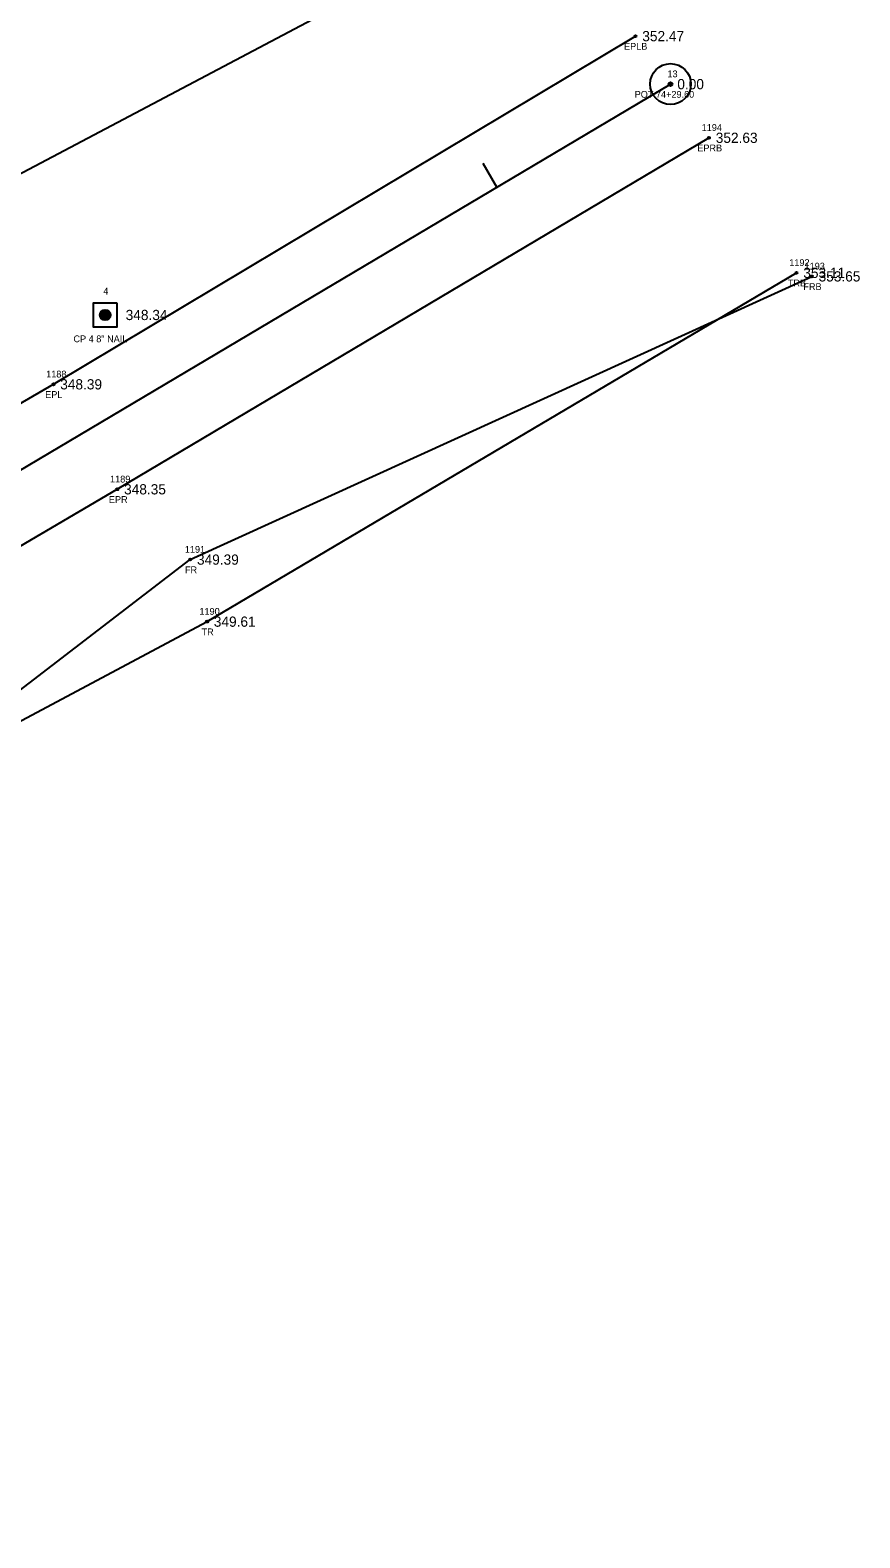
# Model space of a CAD drawing. Extents: x 2231119 to 2232595, y 1035731 to 1037094.
# Drawn here: x 2232187.1 to 2232308.8, y 1036650 to 1036871.1 of the extents above; entities that cross this region are included whole.
import ezdxf

# ---------------------------------------------------------------- set-up
doc = ezdxf.new("R2010")
doc.units = 0
for name, color, linetype in [('RD_EX_Fence_Other', 7, 'Continuous'), ('RD_EX_Fence_Other_txCode', 7, 'Continuous'), ('RD_EX_Road', 7, 'Continuous'), ('RD_EX_Road_txCode', 7, 'Continuous'), ('RD_EX_TX_Fence_Other_ELEV', 7, 'Continuous'), ('RD_EX_TX_Road_ELEV', 7, 'Continuous'), ('RD_EX_TX_VEG_ELEV', 7, 'Continuous'), ('RD_EX_VEG', 7, 'Continuous'), ('RD_EX_VEG_txCode', 7, 'Continuous'), ('RD_HC_Cl', 7, 'Continuous'), ('RD_HC_Data', 7, 'Continuous'), ('RD_HC_Data_Tic', 7, 'Continuous'), ('RD_HC_Survey', 7, 'Continuous'), ('RD_HC_Survey_ELEV', 7, 'Continuous'), ('RD_HC_Survey_txCode', 7, 'Continuous'), ('RD_HC_txCode', 7, 'Continuous'), ('RD_SMD_Locator', 7, 'Continuous')]:
    doc.layers.add(name, color=color, linetype=linetype)

msp = doc.modelspace()

# ---------------------------------------------------------------- linework, layer by layer
at = {"layer": 'RD_EX_Fence_Other'}
msp.add_lwpolyline([(2231742.82, 1036485.51), (2231730.99, 1036494.96), (2231789.88, 1036531.02), (2231876.81, 1036583.89), (2231964.37, 1036635.23), (2232046.18, 1036684.79), (2232133.57, 1036734.4), (2232210.6, 1036793.49), (2232301.78, 1036835.03)], dxfattribs=at)
at = {"layer": 'RD_EX_Road'}
for points in [[(2231606.1, 1036462.92), (2231601.27, 1036470.82), (2231681.58, 1036519.84), (2231764.99, 1036568.78), (2231851.5, 1036619.95), (2231935.62, 1036669.65), (2232021.78, 1036720.22), (2232106.75, 1036770.57), (2232190.54, 1036819.2), (2232275.92, 1036870.27)], [(2231606.1, 1036462.92), (2231610.57, 1036455.36), (2231692.09, 1036503.24), (2231706.07, 1036512.59), (2231777.1, 1036553.27), (2231861.39, 1036604.65), (2231946.39, 1036654.77), (2232031.07, 1036704.2), (2232117.06, 1036755.16), (2232199.91, 1036803.8), (2232286.7, 1036855.36)]]:
    msp.add_lwpolyline(points, dxfattribs=at)
at = {"layer": 'RD_EX_VEG'}
for points in [[(2231598.25, 1036478.35), (2231674.54, 1036527.95), (2231759.25, 1036584.63), (2231839.99, 1036637.88), (2231924.53, 1036692.24), (2232004.98, 1036742.14), (2232090.99, 1036793.16), (2232172.16, 1036843), (2232262.27, 1036890.61)], [(2231753.59, 1036474.98), (2231730.55, 1036496.34), (2231788.45, 1036533.87), (2231871.45, 1036588.79), (2231958.94, 1036639.51), (2232040.64, 1036687.92), (2232130.59, 1036740.48), (2232213.07, 1036784.39), (2232299.54, 1036835.55)]]:
    msp.add_lwpolyline(points, dxfattribs=at)
at = {"layer": 'RD_HC_Cl'}
msp.add_line((2231548.98, 1036428.87), (2232281.06, 1036863.23), dxfattribs=at)
at = {"layer": 'RD_HC_Data'}
for radius in [3, 0.282]:
    msp.add_circle((2232281.06, 1036863.23), radius, dxfattribs=at)
at = {"layer": 'RD_HC_Data_Tic'}
msp.add_line((2232255.6, 1036848.13), (2232253.56, 1036851.57), dxfattribs=at)
at = {"layer": 'RD_HC_Survey'}
for p, q in [((2232197.59, 1036828.83), (2232197.59, 1036829.9)), ((2232197.62, 1036828.8), (2232197.62, 1036829.93)), ((2232197.64, 1036828.78), (2232197.64, 1036829.95)), ((2232197.67, 1036828.76), (2232197.67, 1036829.97)), ((2232197.69, 1036828.74), (2232197.69, 1036829.99)), ((2232197.72, 1036828.73), (2232197.72, 1036830.01)), ((2232197.74, 1036828.71), (2232197.74, 1036830.02)), ((2232197.77, 1036828.7), (2232197.77, 1036830.04)), ((2232197.79, 1036828.68), (2232197.79, 1036830.05)), ((2232197.82, 1036828.67), (2232197.82, 1036830.06)), ((2232197.84, 1036828.66), (2232197.84, 1036830.07)), ((2232197.87, 1036828.65), (2232197.87, 1036830.08)), ((2232197.89, 1036828.64), (2232197.89, 1036830.09)), ((2232197.92, 1036828.63), (2232197.92, 1036830.1)), ((2232197.94, 1036828.62), (2232197.94, 1036830.11)), ((2232197.97, 1036828.62), (2232197.97, 1036830.11)), ((2232197.99, 1036828.61), (2232197.99, 1036830.12)), ((2232198.01, 1036828.61), (2232198.01, 1036830.12)), ((2232198.04, 1036828.6), (2232198.04, 1036830.13)), ((2232198.06, 1036828.6), (2232198.06, 1036830.13)), ((2232198.09, 1036828.6), (2232198.09, 1036830.13)), ((2232198.11, 1036828.6), (2232198.11, 1036830.13)), ((2232198.14, 1036828.6), (2232198.14, 1036830.14)), ((2232198.16, 1036828.6), (2232198.16, 1036830.14)), ((2232198.19, 1036828.6), (2232198.19, 1036830.13)), ((2232198.21, 1036828.6), (2232198.21, 1036830.13)), ((2232198.24, 1036828.6), (2232198.24, 1036830.13)), ((2232198.26, 1036828.61), (2232198.26, 1036830.13)), ((2232198.29, 1036828.61), (2232198.29, 1036830.12)), ((2232198.31, 1036828.62), (2232198.31, 1036830.12)), ((2232198.34, 1036828.62), (2232198.34, 1036830.11)), ((2232198.36, 1036828.63), (2232198.36, 1036830.1)), ((2232198.39, 1036828.64), (2232198.39, 1036830.1)), ((2232198.41, 1036828.64), (2232198.41, 1036830.09)), ((2232198.44, 1036828.65), (2232198.44, 1036830.08)), ((2232198.46, 1036828.66), (2232198.46, 1036830.07)), ((2232198.49, 1036828.68), (2232198.49, 1036830.06)), ((2232198.51, 1036828.69), (2232198.51, 1036830.04)), ((2232198.53, 1036828.7), (2232198.53, 1036830.03)), ((2232198.56, 1036828.72), (2232198.56, 1036830.01)), ((2232198.58, 1036828.73), (2232198.58, 1036830)), ((2232198.61, 1036828.75), (2232198.61, 1036829.98)), ((2232198.63, 1036828.77), (2232198.63, 1036829.96)), ((2232198.66, 1036828.79), (2232198.66, 1036829.94)), ((2232198.68, 1036828.82), (2232198.68, 1036829.92)), ((2232197.4, 1036829.19), (2232197.4, 1036829.55)), ((2232197.42, 1036829.1), (2232197.42, 1036829.63)), ((2232197.45, 1036829.04), (2232197.45, 1036829.69)), ((2232197.47, 1036829), (2232197.47, 1036829.74)), ((2232197.5, 1036828.95), (2232197.5, 1036829.78)), ((2232197.52, 1036828.92), (2232197.52, 1036829.82)), ((2232197.54, 1036828.88), (2232197.54, 1036829.85)), ((2232197.57, 1036828.85), (2232197.57, 1036829.88)), ((2232198.71, 1036828.84), (2232198.71, 1036829.89)), ((2232198.73, 1036828.87), (2232198.73, 1036829.86)), ((2232198.76, 1036828.9), (2232198.76, 1036829.83)), ((2232198.78, 1036828.94), (2232198.78, 1036829.8)), ((2232198.81, 1036828.97), (2232198.81, 1036829.76)), ((2232198.83, 1036829.02), (2232198.83, 1036829.71)), ((2232198.86, 1036829.07), (2232198.86, 1036829.66)), ((2232198.88, 1036829.14), (2232198.88, 1036829.59)), ((2232198.91, 1036829.25), (2232198.91, 1036829.48))]:
    msp.add_line(p, q, dxfattribs=at)
msp.add_lwpolyline([(2232199.89, 1036831.12), (2232196.39, 1036831.12), (2232196.39, 1036827.62), (2232199.89, 1036827.62)], close=True, dxfattribs=at)
msp.add_circle((2232198.14, 1036829.37), 0.769, dxfattribs=at)
at = {"layer": 'RD_SMD_Locator'}
for centre in [(2232275.92, 1036870.27), (2232281.06, 1036863.23), (2232286.7, 1036855.36), (2232299.54, 1036835.55), (2232301.78, 1036835.03), (2232198.14, 1036829.37), (2232190.54, 1036819.2), (2232199.91, 1036803.8), (2232210.6, 1036793.49), (2232213.07, 1036784.39)]:
    msp.add_circle(centre, 0.15, dxfattribs=at)

# ---------------------------------------------------------------- texts
at = {"layer": 'RD_EX_Fence_Other_txCode'}
for s, p in [('1193', (2232300.72, 1036836.03)), ('FRB', (2232300.55, 1036833.03)), ('1191', (2232209.82, 1036794.49)), ('FR', (2232209.84, 1036791.49))]:
    msp.add_text(s, height=1, dxfattribs=at).set_placement(p)
at = {"layer": 'RD_EX_Road_txCode'}
for s, p in [('EPLB', (2232274.24, 1036868.27)), ('1194', (2232285.63, 1036856.36)), ('EPRB', (2232284.99, 1036853.36)), ('1188', (2232189.48, 1036820.2)), ('EPL', (2232189.34, 1036817.2)), ('1189', (2232198.85, 1036804.8)), ('EPR', (2232198.68, 1036801.8))]:
    msp.add_text(s, height=1, dxfattribs=at).set_placement(p)
at = {"layer": 'RD_EX_TX_Fence_Other_ELEV'}
for s, p in [('353.65', (2232302.78, 1036834.28)), ('349.39', (2232211.6, 1036792.74))]:
    msp.add_text(s, height=1.5, dxfattribs=at).set_placement(p)
at = {"layer": 'RD_EX_TX_Road_ELEV'}
for s, p in [('352.47', (2232276.92, 1036869.52)), ('352.63', (2232287.7, 1036854.61)), ('348.39', (2232191.54, 1036818.45)), ('348.35', (2232200.91, 1036803.05))]:
    msp.add_text(s, height=1.5, dxfattribs=at).set_placement(p)
at = {"layer": 'RD_EX_TX_VEG_ELEV'}
for s, p in [('353.11', (2232300.54, 1036834.8)), ('349.61', (2232214.07, 1036783.64))]:
    msp.add_text(s, height=1.5, dxfattribs=at).set_placement(p)
at = {"layer": 'RD_EX_VEG_txCode'}
for s, p in [('1192', (2232298.48, 1036836.55)), ('TRB', (2232298.27, 1036833.55)), ('1190', (2232211.96, 1036785.39)), ('TR', (2232212.27, 1036782.39))]:
    msp.add_text(s, height=1, dxfattribs=at).set_placement(p)
at = {"layer": 'RD_HC_Survey_ELEV'}
for s, p in [('0.00', (2232282.06, 1036862.48)), ('348.34', (2232201.14, 1036828.62))]:
    msp.add_text(s, height=1.5, dxfattribs=at).set_placement(p)
at = {"layer": 'RD_HC_Survey_txCode'}
for s, p in [('4', (2232197.86, 1036832.37)), ('CP 4 8" NAIL', (2232193.48, 1036825.37))]:
    msp.add_text(s, height=1, dxfattribs=at).set_placement(p)
at = {"layer": 'RD_HC_txCode'}
for s, p in [('13', (2232280.61, 1036864.23)), ('POT 74+29.60', (2232275.8, 1036861.23))]:
    msp.add_text(s, height=1, dxfattribs=at).set_placement(p)

doc.saveas('drawing.dxf')
